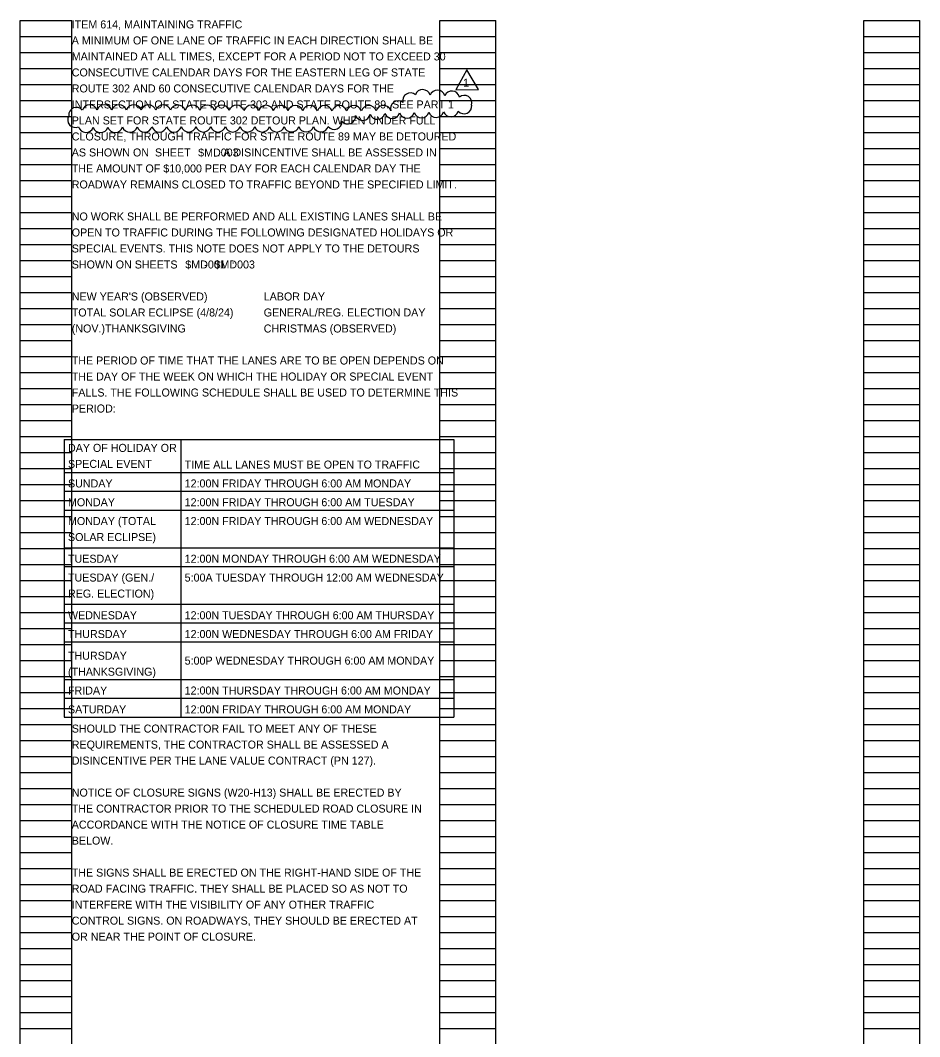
# Model space of a CAD drawing. Extents: x -9 to 32, y -122 to 20.
# Drawn here: x 1.22 to 16.96, y 2.69 to 20.47 of the extents above; entities that cross this region are included whole.
import ezdxf

# ---------------------------------------------------------------- set-up
doc = ezdxf.new("R2010")
doc.units = 0
for name, color, linetype in [('SC_Scratch1', 7, 'Continuous'), ('SH_Text', 7, 'Continuous'), ('TX_P_1', 7, 'Continuous')]:
    doc.layers.add(name, color=color, linetype=linetype)

msp = doc.modelspace()

# ---------------------------------------------------------------- linework, layer by layer
at = {"layer": 'SC_Scratch1'}
for p, q in [((1.216, 0.306), (1.216, 20.466)), ((1.216, 20.466), (2.116, 20.466)), ((2.116, 0.306), (2.116, 20.466)), ((8.556, 0.306), (8.556, 20.466)), ((8.556, 20.466), (9.536, 20.466)), ((9.536, 0.306), (9.536, 20.466)), ((15.976, 0.306), (15.976, 20.466)), ((15.976, 20.466), (16.956, 20.466)), ((16.956, 0.306), (16.956, 20.466)), ((1.216, 20.186), (2.116, 20.186)), ((8.556, 20.186), (9.536, 20.186)), ((15.976, 20.186), (16.956, 20.186)), ((1.216, 19.906), (2.116, 19.906)), ((8.556, 19.906), (9.536, 19.906)), ((15.976, 19.906), (16.956, 19.906)), ((1.216, 19.626), (2.116, 19.626)), ((8.556, 19.626), (9.536, 19.626)), ((15.976, 19.626), (16.956, 19.626)), ((1.216, 19.346), (2.116, 19.346)), ((8.556, 19.346), (9.536, 19.346)), ((15.976, 19.346), (16.956, 19.346)), ((1.216, 19.066), (2.116, 19.066)), ((8.556, 19.066), (9.536, 19.066)), ((15.976, 19.066), (16.956, 19.066)), ((1.216, 18.786), (2.116, 18.786)), ((8.556, 18.786), (9.536, 18.786)), ((15.976, 18.786), (16.956, 18.786)), ((1.216, 18.506), (2.116, 18.506)), ((8.556, 18.506), (9.536, 18.506)), ((15.976, 18.506), (16.956, 18.506)), ((1.216, 18.226), (2.116, 18.226)), ((8.556, 18.226), (9.536, 18.226)), ((15.976, 18.226), (16.956, 18.226)), ((1.216, 17.946), (2.116, 17.946)), ((8.556, 17.946), (9.536, 17.946)), ((15.976, 17.946), (16.956, 17.946)), ((1.216, 17.666), (2.116, 17.666)), ((8.556, 17.666), (9.536, 17.666)), ((15.976, 17.666), (16.956, 17.666)), ((1.216, 17.386), (2.116, 17.386)), ((8.556, 17.386), (9.536, 17.386)), ((15.976, 17.386), (16.956, 17.386)), ((1.216, 17.106), (2.116, 17.106)), ((8.556, 17.106), (9.536, 17.106)), ((15.976, 17.106), (16.956, 17.106)), ((1.216, 16.826), (2.116, 16.826)), ((8.556, 16.826), (9.536, 16.826)), ((15.976, 16.826), (16.956, 16.826)), ((1.216, 16.546), (2.116, 16.546)), ((8.556, 16.546), (9.536, 16.546)), ((15.976, 16.546), (16.956, 16.546)), ((1.216, 16.266), (2.116, 16.266)), ((8.556, 16.266), (9.536, 16.266)), ((15.976, 16.266), (16.956, 16.266)), ((1.216, 15.986), (2.116, 15.986)), ((8.556, 15.986), (9.536, 15.986)), ((15.976, 15.986), (16.956, 15.986)), ((1.216, 15.706), (2.116, 15.706)), ((8.556, 15.706), (9.536, 15.706)), ((15.976, 15.706), (16.956, 15.706)), ((1.216, 15.426), (2.116, 15.426)), ((8.556, 15.426), (9.536, 15.426)), ((15.976, 15.426), (16.956, 15.426)), ((1.216, 15.146), (2.116, 15.146)), ((8.556, 15.146), (9.536, 15.146)), ((15.976, 15.146), (16.956, 15.146)), ((1.216, 14.866), (2.116, 14.866)), ((8.556, 14.866), (9.536, 14.866)), ((15.976, 14.866), (16.956, 14.866)), ((1.216, 14.586), (2.116, 14.586)), ((8.556, 14.586), (9.536, 14.586)), ((15.976, 14.586), (16.956, 14.586)), ((1.216, 14.306), (2.116, 14.306)), ((8.556, 14.306), (9.536, 14.306)), ((15.976, 14.306), (16.956, 14.306)), ((1.216, 14.026), (2.116, 14.026)), ((8.556, 14.026), (9.536, 14.026)), ((15.976, 14.026), (16.956, 14.026)), ((1.216, 13.746), (2.116, 13.746)), ((8.556, 13.746), (9.536, 13.746)), ((15.976, 13.746), (16.956, 13.746)), ((1.216, 13.466), (2.116, 13.466)), ((8.556, 13.466), (9.536, 13.466)), ((15.976, 13.466), (16.956, 13.466)), ((1.216, 13.186), (2.116, 13.186)), ((8.556, 13.186), (9.536, 13.186)), ((15.976, 13.186), (16.956, 13.186)), ((1.216, 12.906), (2.116, 12.906)), ((8.556, 12.906), (9.536, 12.906)), ((15.976, 12.906), (16.956, 12.906)), ((1.216, 12.626), (2.116, 12.626)), ((8.556, 12.626), (9.536, 12.626)), ((15.976, 12.626), (16.956, 12.626)), ((1.216, 12.346), (2.116, 12.346)), ((8.556, 12.346), (9.536, 12.346)), ((15.976, 12.346), (16.956, 12.346)), ((1.216, 12.066), (2.116, 12.066)), ((8.556, 12.066), (9.536, 12.066)), ((15.976, 12.066), (16.956, 12.066)), ((1.216, 11.786), (2.116, 11.786)), ((8.556, 11.786), (9.536, 11.786)), ((15.976, 11.786), (16.956, 11.786)), ((1.216, 11.506), (2.116, 11.506)), ((8.556, 11.506), (9.536, 11.506)), ((15.976, 11.506), (16.956, 11.506)), ((1.216, 11.226), (2.116, 11.226)), ((8.556, 11.226), (9.536, 11.226)), ((15.976, 11.226), (16.956, 11.226)), ((1.216, 10.946), (2.116, 10.946)), ((8.556, 10.946), (9.536, 10.946)), ((15.976, 10.946), (16.956, 10.946)), ((1.216, 10.666), (2.116, 10.666)), ((8.556, 10.666), (9.536, 10.666)), ((15.976, 10.666), (16.956, 10.666)), ((1.216, 10.386), (2.116, 10.386)), ((8.556, 10.386), (9.536, 10.386)), ((15.976, 10.386), (16.956, 10.386)), ((1.216, 10.106), (2.116, 10.106)), ((8.556, 10.106), (9.536, 10.106)), ((15.976, 10.106), (16.956, 10.106)), ((1.216, 9.826), (2.116, 9.826)), ((8.556, 9.826), (9.536, 9.826)), ((15.976, 9.826), (16.956, 9.826)), ((1.216, 9.546), (2.116, 9.546)), ((8.556, 9.546), (9.536, 9.546)), ((15.976, 9.546), (16.956, 9.546)), ((1.216, 9.266), (2.116, 9.266)), ((8.556, 9.266), (9.536, 9.266)), ((15.976, 9.266), (16.956, 9.266)), ((1.216, 8.986), (2.116, 8.986)), ((8.556, 8.986), (9.536, 8.986)), ((15.976, 8.986), (16.956, 8.986)), ((1.216, 8.706), (2.116, 8.706)), ((8.556, 8.706), (9.536, 8.706)), ((15.976, 8.706), (16.956, 8.706)), ((1.216, 8.426), (2.116, 8.426)), ((8.556, 8.426), (9.536, 8.426)), ((15.976, 8.426), (16.956, 8.426)), ((1.216, 8.146), (2.116, 8.146)), ((8.556, 8.146), (9.536, 8.146)), ((15.976, 8.146), (16.956, 8.146)), ((1.216, 7.866), (2.116, 7.866)), ((8.556, 7.866), (9.536, 7.866)), ((15.976, 7.866), (16.956, 7.866)), ((1.216, 7.586), (2.116, 7.586)), ((8.556, 7.586), (9.536, 7.586)), ((15.976, 7.586), (16.956, 7.586)), ((1.216, 7.306), (2.116, 7.306)), ((8.556, 7.306), (9.536, 7.306)), ((15.976, 7.306), (16.956, 7.306)), ((1.216, 7.026), (2.116, 7.026)), ((8.556, 7.026), (9.536, 7.026)), ((15.976, 7.026), (16.956, 7.026)), ((1.216, 6.746), (2.116, 6.746)), ((8.556, 6.746), (9.536, 6.746)), ((15.976, 6.746), (16.956, 6.746)), ((1.216, 6.466), (2.116, 6.466)), ((8.556, 6.466), (9.536, 6.466)), ((15.976, 6.466), (16.956, 6.466)), ((1.216, 6.186), (2.116, 6.186)), ((8.556, 6.186), (9.536, 6.186)), ((15.976, 6.186), (16.956, 6.186)), ((1.216, 5.906), (2.116, 5.906)), ((8.556, 5.906), (9.536, 5.906)), ((15.976, 5.906), (16.956, 5.906)), ((1.216, 5.626), (2.116, 5.626)), ((8.556, 5.626), (9.536, 5.626)), ((15.976, 5.626), (16.956, 5.626)), ((1.216, 5.346), (2.116, 5.346)), ((8.556, 5.346), (9.536, 5.346)), ((15.976, 5.346), (16.956, 5.346)), ((1.216, 5.066), (2.116, 5.066)), ((8.556, 5.066), (9.536, 5.066)), ((15.976, 5.066), (16.956, 5.066)), ((1.216, 4.786), (2.116, 4.786)), ((8.556, 4.786), (9.536, 4.786)), ((15.976, 4.786), (16.956, 4.786)), ((1.216, 4.506), (2.116, 4.506)), ((8.556, 4.506), (9.536, 4.506)), ((15.976, 4.506), (16.956, 4.506)), ((1.216, 4.226), (2.116, 4.226)), ((8.556, 4.226), (9.536, 4.226)), ((15.976, 4.226), (16.956, 4.226)), ((1.216, 3.946), (2.116, 3.946)), ((8.556, 3.946), (9.536, 3.946)), ((15.976, 3.946), (16.956, 3.946)), ((1.216, 3.666), (2.116, 3.666)), ((8.556, 3.666), (9.536, 3.666)), ((15.976, 3.666), (16.956, 3.666)), ((1.216, 3.386), (2.116, 3.386)), ((8.556, 3.386), (9.536, 3.386)), ((15.976, 3.386), (16.956, 3.386)), ((1.216, 3.106), (2.116, 3.106)), ((8.556, 3.106), (9.536, 3.106)), ((15.976, 3.106), (16.956, 3.106)), ((1.216, 2.826), (2.116, 2.826)), ((8.556, 2.826), (9.536, 2.826)), ((15.976, 2.826), (16.956, 2.826))]:
    msp.add_line(p, q, dxfattribs=at)
at = {"layer": 'SH_Text'}
for p, q in [((1.984, 13.135), (8.803, 13.135)), ((1.984, 13.135), (1.984, 8.277)), ((4.026, 13.135), (4.026, 8.277)), ((8.803, 13.135), (8.803, 8.277)), ((1.984, 12.559), (8.803, 12.559)), ((1.984, 12.229), (8.803, 12.229)), ((1.984, 11.9), (8.803, 11.9)), ((1.984, 11.241), (8.803, 11.241)), ((1.984, 10.912), (8.803, 10.912)), ((1.984, 10.253), (8.803, 10.253)), ((1.984, 9.924), (8.803, 9.924)), ((1.984, 9.924), (8.803, 9.924)), ((1.984, 9.594), (8.803, 9.594)), ((1.984, 8.935), (8.803, 8.935)), ((1.984, 8.606), (8.803, 8.606)), ((1.984, 8.277), (8.803, 8.277))]:
    msp.add_line(p, q, dxfattribs=at)
at = {"layer": 'TX_P_1'}
msp.add_lwpolyline([(9.234, 19.259), (9.03, 19.601), (8.836, 19.253)], close=True, dxfattribs=at)
for centre, start, end in [((8.258, 19.121), 15.9725, 160.9725), ((8.515, 19.113), 15.3275, 160.3275), ((8.769, 19.096), 12.3572, 157.3572), ((7.829, 18.924), 52.3257, 197.3257), ((8.042, 19.063), 48.836, 193.836), ((8.985, 19.02), 343.8387, 128.8387), ((2.197, 18.809), 39.7437, 184.7437), ((2.43, 18.855), 17.6942, 162.6942), ((2.687, 18.855), 17.4786, 162.4786), ((2.944, 18.855), 17.3985, 162.3985), ((3.201, 18.855), 17.3528, 162.3528), ((3.458, 18.854), 17.3223, 162.3223), ((3.715, 18.853), 17.3, 162.3), ((3.972, 18.852), 17.2829, 162.2829), ((4.229, 18.851), 17.2691, 162.2691), ((4.486, 18.85), 17.2578, 162.2578), ((4.743, 18.849), 17.2482, 162.2482), ((5, 18.848), 17.2426, 162.2426), ((5.258, 18.847), 17.2527, 162.2527), ((5.515, 18.846), 17.2671, 162.2671), ((5.772, 18.845), 17.2841, 162.2841), ((6.029, 18.844), 17.3047, 162.3047), ((6.286, 18.843), 17.3305, 162.3305), ((6.543, 18.842), 17.364, 162.364), ((6.8, 18.842), 17.4099, 162.4099), ((7.057, 18.841), 17.4787, 162.4787), ((7.315, 18.842), 17.6, 162.6), ((7.572, 18.843), 17.9308, 162.9308), ((7.98, 18.891), 198.9131, 343.9131), ((8.237, 18.897), 198.9967, 343.9967), ((8.494, 18.904), 199.1904, 344.1904), ((8.75, 18.913), 199.6002, 344.6002), ((8.981, 18.967), 221.7776, 6.7776), ((2.179, 18.729), 149.197, 294.197), ((6.71, 18.695), 218.515, 3.515), ((6.948, 18.789), 219.6029, 4.6029), ((7.207, 18.852), 202.8836, 347.8836), ((7.465, 18.871), 200.6217, 345.6217), ((7.723, 18.883), 199.4751, 344.4751), ((2.364, 18.642), 195.5185, 340.5185), ((2.619, 18.638), 197.9343, 342.9343), ((2.876, 18.641), 198.1746, 343.1746), ((3.133, 18.643), 197.9461, 342.9461), ((3.391, 18.645), 197.8109, 342.8109), ((3.648, 18.646), 197.7188, 342.7188), ((3.905, 18.647), 197.6509, 342.6509), ((4.162, 18.648), 197.5981, 342.5981), ((4.419, 18.648), 197.5555, 342.5555), ((4.676, 18.648), 197.5202, 342.5202), ((4.933, 18.648), 197.4906, 342.4906), ((5.191, 18.648), 197.4924, 342.4924), ((5.448, 18.648), 197.5184, 342.5184), ((5.705, 18.648), 197.5532, 342.5532), ((5.962, 18.649), 197.6033, 342.6033), ((6.219, 18.649), 197.6849, 342.6849), ((6.476, 18.651), 197.8588, 342.8588)]:
    msp.add_arc(centre, 0.135, start, end, dxfattribs=at)

# ---------------------------------------------------------------- texts
at = {"layer": 'SH_Text'}
for s, p in [('ITEM 614, MAINTAINING TRAFFIC', (2.116, 20.326)), ('A MINIMUM OF ONE LANE OF TRAFFIC IN EACH DIRECTION SHALL BE ', (2.116, 20.046)), ('MAINTAINED AT ALL TIMES, EXCEPT FOR A PERIOD NOT TO EXCEED 30 ', (2.116, 19.766)), ('CONSECUTIVE CALENDAR DAYS FOR THE EASTERN LEG OF STATE ', (2.116, 19.486)), ('ROUTE 302 AND 60 CONSECUTIVE CALENDAR DAYS FOR THE ', (2.116, 19.206)), ('INTERSECTION OF STATE ROUTE 302 AND STATE ROUTE 89. SEE PART 1 ', (2.116, 18.926)), ('PLAN SET FOR STATE ROUTE 302 DETOUR PLAN. WHEN UNDER FULL ', (2.116, 18.646)), ('CLOSURE, THROUGH TRAFFIC FOR STATE ROUTE 89 MAY BE DETOURED ', (2.116, 18.366)), ('AS SHOWN ON  SHEET         . A DISINCENTIVE SHALL BE ASSESSED IN ', (2.116, 18.086)), ('$MD003', (4.328, 18.085)), ('THE AMOUNT OF $10,000 PER DAY FOR EACH CALENDAR DAY THE ', (2.116, 17.806)), ('ROADWAY REMAINS CLOSED TO TRAFFIC BEYOND THE SPECIFIED LIMIT. ', (2.116, 17.526)), ('NO WORK SHALL BE PERFORMED AND ALL EXISTING LANES SHALL BE ', (2.116, 16.966)), ('OPEN TO TRAFFIC DURING THE FOLLOWING DESIGNATED HOLIDAYS OR ', (2.116, 16.686)), ('SPECIAL EVENTS. THIS NOTE DOES NOT APPLY TO THE DETOURS ', (2.116, 16.406)), ('SHOWN ON SHEETS         -        :', (2.116, 16.126)), ('$MD001', (4.103, 16.126)), ('$MD003', (4.614, 16.126)), ("NEW YEAR'S (OBSERVED)", (2.116, 15.566)), ('LABOR DAY', (5.476, 15.566)), ('TOTAL SOLAR ECLIPSE (4/8/24) ', (2.116, 15.286)), ('GENERAL/REG. ELECTION DAY ', (5.476, 15.286)), ('(NOV.)THANKSGIVING', (2.116, 15.006)), ('CHRISTMAS (OBSERVED)', (5.476, 15.006)), ('THE PERIOD OF TIME THAT THE LANES ARE TO BE OPEN DEPENDS ON ', (2.116, 14.446)), ('THE DAY OF THE WEEK ON WHICH THE HOLIDAY OR SPECIAL EVENT ', (2.116, 14.166)), ('FALLS. THE FOLLOWING SCHEDULE SHALL BE USED TO DETERMINE THIS ', (2.116, 13.886)), ('PERIOD:', (2.116, 13.606)), ('DAY OF HOLIDAY OR ', (2.05, 12.917)), ('SPECIAL EVENT', (2.05, 12.637)), ('TIME ALL LANES MUST BE OPEN TO TRAFFIC', (4.092, 12.625)), ('SUNDAY', (2.05, 12.295)), ('12:00N FRIDAY THROUGH 6:00 AM MONDAY', (4.092, 12.295)), ('MONDAY', (2.05, 11.966)), ('12:00N FRIDAY THROUGH 6:00 AM TUESDAY', (4.092, 11.966)), ('MONDAY (TOTAL', (2.05, 11.637)), ('12:00N FRIDAY THROUGH 6:00 AM WEDNESDAY', (4.092, 11.637)), ('SOLAR ECLIPSE)', (2.05, 11.357)), ('TUESDAY', (2.05, 10.978)), ('12:00N MONDAY THROUGH 6:00 AM WEDNESDAY', (4.092, 10.978)), ('TUESDAY (GEN./', (2.05, 10.648)), ('5:00A TUESDAY THROUGH 12:00 AM WEDNESDAY', (4.092, 10.648)), ('REG. ELECTION)', (2.05, 10.368)), ('WEDNESDAY', (2.05, 9.989)), ('12:00N TUESDAY THROUGH 6:00 AM THURSDAY', (4.092, 9.989)), ('THURSDAY', (2.05, 9.66)), ('12:00N WEDNESDAY THROUGH 6:00 AM FRIDAY', (4.092, 9.66)), ('THURSDAY ', (2.05, 9.281)), ('5:00P WEDNESDAY THROUGH 6:00 AM MONDAY', (4.092, 9.195)), ('(THANKSGIVING)', (2.05, 9.001)), ('FRIDAY', (2.05, 8.672)), ('12:00N THURSDAY THROUGH 6:00 AM MONDAY', (4.092, 8.672)), ('SATURDAY', (2.05, 8.342)), ('12:00N FRIDAY THROUGH 6:00 AM MONDAY', (4.092, 8.342)), ('SHOULD THE CONTRACTOR FAIL TO MEET ANY OF THESE ', (2.116, 8.006)), ('REQUIREMENTS, THE CONTRACTOR SHALL BE ASSESSED A ', (2.116, 7.726)), ('DISINCENTIVE PER THE LANE VALUE CONTRACT (PN 127).', (2.116, 7.446)), ('NOTICE OF CLOSURE SIGNS (W20-H13) SHALL BE ERECTED BY ', (2.116, 6.886)), ('THE CONTRACTOR PRIOR TO THE SCHEDULED ROAD CLOSURE IN ', (2.116, 6.606)), ('ACCORDANCE WITH THE NOTICE OF CLOSURE TIME TABLE ', (2.116, 6.326)), ('BELOW.', (2.116, 6.046)), ('THE SIGNS SHALL BE ERECTED ON THE RIGHT-HAND SIDE OF THE ', (2.116, 5.486)), ('ROAD FACING TRAFFIC. THEY SHALL BE PLACED SO AS NOT TO ', (2.116, 5.206)), ('INTERFERE WITH THE VISIBILITY OF ANY OTHER TRAFFIC ', (2.116, 4.926)), ('CONTROL SIGNS. ON ROADWAYS, THEY SHOULD BE ERECTED AT ', (2.116, 4.646)), ('OR NEAR THE POINT OF CLOSURE. ', (2.116, 4.366))]:
    msp.add_text(s, height=0.14, dxfattribs=at).set_placement(p)
at = {"layer": 'TX_P_1'}
msp.add_text('1', height=0.14, dxfattribs=at).set_placement((8.965, 19.307))

doc.saveas('drawing.dxf')
